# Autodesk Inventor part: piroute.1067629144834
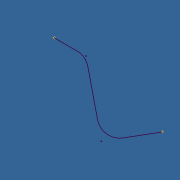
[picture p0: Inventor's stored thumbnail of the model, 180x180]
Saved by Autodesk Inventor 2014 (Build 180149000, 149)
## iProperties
StyleName: _Piping Style 7
Company: Autodesk, Inc.
Part Number: piroute.1067629144834
Document SubType Name: Tube & Pipe
Created: 2003-10
Designer: Autodesk, Inc.
Manufacturer: Standard
Standards Organization: Custom
Density: 1 g/cm^3
Material: Generic
Appearance: Default
TPVersion: 11.0.2
ActiveState: True
Angle: UnInitValue
BendRadius: UnInitValue
CouplingKey: v3#0dc1ae02-7bbf-4ccf-8498-581434b0a765#3
DefaultBendRadius: 2.000 in
Diameter: 1/2
DiameterType: Nominal
Elbow45Key: UnInitValue
Elbow90Key: UnInitValue
ElbowCustomKey: UnInitValue
EndFittingKey: UnInitValue
Ending: UnInitValue
FittingMaterial: UnInitValue
FittingStandard: UnInitValue
FlangeKey: UnInitValue
Gap: UnInitValue
GasketKey: UnInitValue
ID: UnInitValue
IntermediateSegmentsInc: 0.100 in
IntermediateSegmentsMax: 100.000 in
IntermediateSegmentsMin: 0.000 in
IsButtWelded: UnInitValue
IsFlanged: UnInitValue
IsSelfDraining: UnInitValue
Material: UnInitValue
MixedUnits: UnInitValue
Name: ASTM B 88-ASME B16.22 - Soldered Copper Tubing
OD: UnInitValue
PipeKey: v3#44b182c9-4bce-4825-bb4d-596143122252#7
PipeType: Tubing
PipingComponentColor: As Material
RoundUpValue: UnInitValue
RouteDirection45: UnInitValue
RouteDirection90: UnInitValue
Schedule: L
ShowGap: UnInitValue
Standard: UnInitValue
StartFittingKey: UnInitValue
SuppressEndFitting: UnInitValue
SuppressStartFitting: UnInitValue
TerminationSegmentsInc: 0.100 in
TerminationSegmentsMax: 100.000 in
TerminationSegmentsMin: 0.000 in
UseFlangsForCouplings: UnInitValue
UseSubASM: UnInitValue
_ComponentInfo: <CS><C N="Pipe" R="0.793750" OR="0.793750" IR="0.692150" PL="PL" PartType="pipe" SymKey="" PN="ASTM B 88 Tube 1/2 - Type L"><CO N="1"><FE V="0"/><FD V="0"/><ET 
Control State: 0
Master: False
Checked Out: False
Shininess: 64.0
Length Units: 11272
Angle Units: 11279
Time Units: 11290
Mass Units: 11286
Length Display Precision: 3
Angle Display Precision: 2
Compacted: True
Density: 0.0
Volumn: 0.0
Area: 0.0
PropertySet Name: Model Information
Author: Autodesk, Inc.
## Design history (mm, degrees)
workpoint "Work Point1"
workpoint "Work Point7"
workplane "Work Plane1"
workplane "Work Plane2"
sketch "3D Sketch1" dims "d2" = 50.8 (= B), "d3" = 50.8 (= B)
other parameters: "B" = 50.8 [user parameter; used in 2 equation terms]
